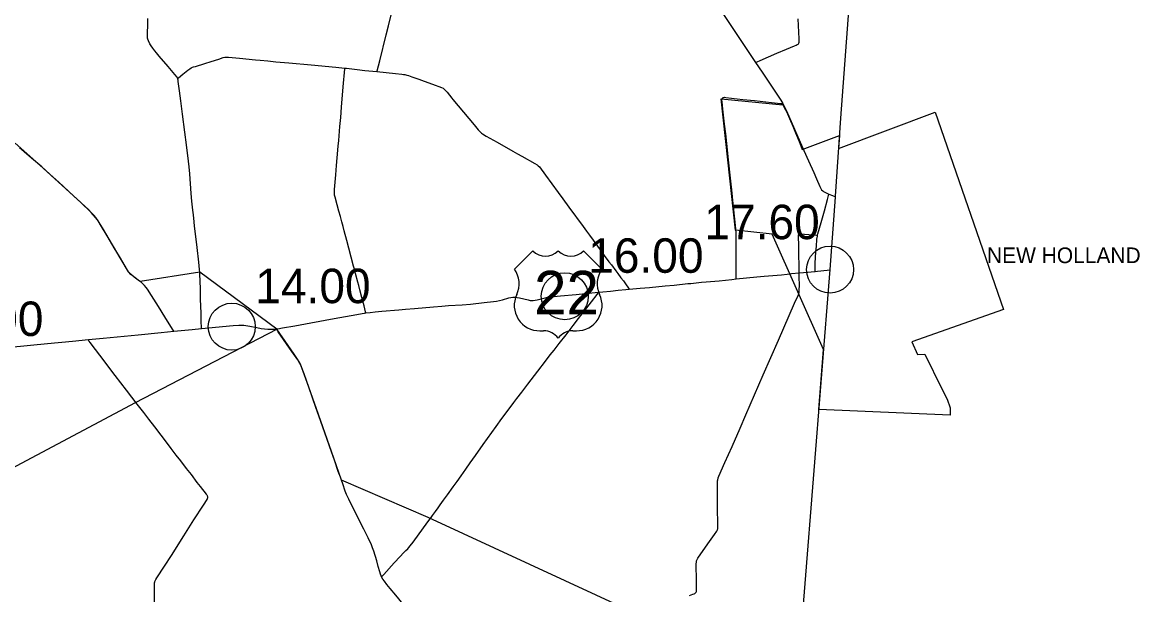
# Model space of a CAD drawing. Extents: x 1597222 to 1925846, y 496284 to 911751.
# Drawn here: x 1727439 to 1763107, y 556061 to 574335 of the extents above; entities that cross this region are included whole.
import ezdxf

# ---------------------------------------------------------------- set-up
doc = ezdxf.new("R2010")
doc.units = 0
for name, color, linetype in [('Default', 7, 'Continuous'), ('GM_X_City_Street', 7, 'Continuous'), ('GM_X_Corporation', 7, 'Continuous'), ('GM_X_Corporation_Text', 7, 'Continuous'), ('GM_X_County', 7, 'Continuous'), ('GM_X_County_Road', 7, 'Continuous'), ('GM_X_Township', 7, 'Continuous'), ('GM_X_Township_Road', 7, 'Continuous'), ('GM_X_US_Route', 7, 'Continuous'), ('GM_X_US_Shield', 7, 'Continuous')]:
    doc.layers.add(name, color=color, linetype=linetype)

msp = doc.modelspace()

# ---------------------------------------------------------------- linework, layer by layer
at = {"layer": 'Default'}
for centre in [(1753223, 566439), (1753223, 566439), (1744754, 565588), (1744754, 565588), (1734126, 564618), (1734126, 564618)]:
    msp.add_circle(centre, 750, dxfattribs=at)
at = {"layer": 'GM_X_City_Street'}
for points in [[(1752369, 570291), (1752389, 570247), (1752536, 569913), (1752703, 569539), (1752788, 569343), (1752900, 569089), (1752929, 569031), (1752955, 568990), (1752988, 568955), (1753013, 568935), (1753055, 568910), (1753188, 568853)], [(1752825, 567538), (1752836, 567586), (1752941, 567949), (1753043, 568312), (1753145, 568676), (1753188, 568853)], [(1753188, 568853), (1753301, 568804), (1753395, 568764)], [(1752239, 566334), (1752234, 566572), (1752227, 566915), (1752223, 567182), (1752217, 567525), (1752218, 567535), (1752218, 567543), (1752220, 567550), (1752221, 567555), (1752223, 567560), (1752226, 567566), (1752230, 567571), (1752235, 567575), (1752242, 567580), (1752251, 567584), (1752260, 567585), (1752270, 567586), (1752550, 567560), (1752746, 567546), (1752795, 567542), (1752825, 567538)], [(1752750, 566381), (1752750, 566403), (1752748, 566509), (1752749, 566657), (1752758, 566820), (1752774, 567017), (1752787, 567180), (1752806, 567409), (1752819, 567506), (1752825, 567538)], [(1752226, 565670), (1752228, 565675), (1752232, 565692), (1752235, 565703), (1752237, 565717), (1752239, 565733), (1752240, 565747), (1752241, 565777), (1752243, 565958), (1752242, 566185), (1752239, 566334)]]:
    msp.add_lwpolyline(points, dxfattribs=at)
at = {"layer": 'GM_X_Corporation'}
msp.add_lwpolyline([(1749745, 571890), (1751716, 571701), (1751801, 571545), (1751863, 571416), (1751961, 571194), (1752034, 571019), (1752121, 570810), (1752184, 570658), (1752255, 570482), (1752338, 570280), (1753522, 570727), (1753491, 570310), (1756577, 571472), (1758765, 565171), (1755833, 564137), (1756019, 563730), (1756253, 563741), (1756795, 562636), (1756958, 562307), (1757061, 562024), (1757061, 561796), (1752864, 561969), (1753016, 563885), (1751378, 567567), (1750207, 567702), (1749959, 569949)], close=True, dxfattribs=at)
at = {"layer": 'GM_X_County'}
msp.add_lwpolyline([(1724957, 620538), (1728386, 620349), (1731998, 620173), (1732995, 620100), (1742304, 619412), (1747296, 619048), (1751520, 618741), (1756758, 618359), (1755763, 604727), (1755032, 592905), (1754900, 590773), (1754843, 589851), (1754339, 581698), (1753562, 571274), (1753386, 568784), (1753383, 568749), (1753220, 566444), (1752151, 553079)], dxfattribs=at)
at = {"layer": 'GM_X_County_Road'}
for points in [[(1749047, 575739), (1749287, 575381), (1749764, 574674), (1749864, 574524), (1750804, 573121), (1750848, 573055)], [(1750848, 573055), (1751060, 572740), (1751399, 572237), (1751653, 571854), (1751721, 571742)], [(1751721, 571742), (1751748, 571684), (1751828, 571510), (1752348, 570341), (1752369, 570291)], [(1731184, 566070), (1731014, 566199), (1730924, 566270), (1730875, 566314), (1730843, 566352), (1730797, 566420), (1730537, 566857), (1730370, 567140), (1730144, 567521), (1729934, 567872), (1729855, 567997), (1729780, 568104), (1729717, 568180), (1729640, 568264), (1729547, 568356), (1729197, 568679), (1728932, 568923), (1728727, 569112), (1728512, 569314), (1728317, 569489), (1728058, 569716), (1727734, 569993), (1727499, 570198), (1727353, 570330)], [(1732277, 564471), (1732256, 564503), (1732176, 564627), (1731988, 564927), (1731782, 565261), (1731566, 565608), (1731434, 565815), (1731396, 565868), (1731344, 565931), (1731299, 565977), (1731228, 566036), (1731184, 566070)], [(1748738, 556034), (1748846, 556072), (1748891, 556091), (1748905, 556100), (1748917, 556109), (1748929, 556119), (1748939, 556131), (1748948, 556144), (1748955, 556160), (1748959, 556174), (1748962, 556187), (1748964, 556205), (1748965, 556270), (1748957, 556631), (1748954, 556910), (1748952, 557041), (1748954, 557070), (1748955, 557091), (1748959, 557116), (1748964, 557140), (1748973, 557167), (1748981, 557187), (1749006, 557231), (1749098, 557367), (1749370, 557757), (1749530, 557985), (1749605, 558093), (1749626, 558131), (1749632, 558145), (1749636, 558160), (1749641, 558184), (1749643, 558213), (1749643, 558312), (1749635, 558820), (1749631, 559099), (1749629, 559230), (1749627, 559427), (1749626, 559591), (1749629, 559674), (1749632, 559700), (1749636, 559723), (1749641, 559746), (1749648, 559770), (1749657, 559794), (1749678, 559848), (1749870, 560283), (1750096, 560793), (1750353, 561379), (1750536, 561800), (1751092, 563079), (1751334, 563636), (1751578, 564192), (1752094, 565363), (1752205, 565613), (1752226, 565670)], [(1737623, 559721), (1737591, 559812), (1737526, 559998), (1737410, 560322), (1737252, 560771), (1737155, 561050), (1736965, 561593), (1736806, 562041), (1736581, 562691), (1736433, 563108), (1736343, 563355), (1736311, 563431), (1736299, 563455), (1736280, 563489), (1736236, 563559), (1736047, 563827), (1735610, 564450), (1735581, 564499), (1735562, 564549)], [(1731010, 562272), (1730938, 562367), (1730767, 562588), (1730588, 562822), (1730407, 563055), (1730267, 563237), (1730048, 563524), (1729772, 563891), (1729601, 564112), (1729574, 564153), (1729563, 564168), (1729546, 564204)], [(1731065, 562201), (1731010, 562272)], [(1731658, 555625), (1731657, 556314), (1731657, 556397), (1731660, 556424), (1731663, 556446), (1731667, 556462), (1731670, 556469), (1731673, 556478), (1731682, 556498), (1731693, 556520), (1731704, 556541), (1731736, 556594), (1731975, 556967), (1732196, 557312), (1732590, 557936), (1732917, 558448), (1733219, 558916), (1733335, 559096), (1733349, 559125), (1733354, 559140), (1733356, 559147), (1733357, 559156), (1733358, 559162), (1733358, 559170), (1733356, 559186), (1733353, 559201), (1733349, 559213), (1733341, 559229), (1733314, 559270), (1733124, 559517), (1733024, 559647), (1732835, 559895), (1732684, 560089), (1732494, 560336), (1732354, 560518), (1732195, 560727), (1732005, 560974), (1731866, 561157), (1731666, 561417), (1731477, 561664), (1731317, 561872), (1731065, 562201)], [(1738909, 556629), (1738891, 556666), (1738873, 556712), (1738850, 556790), (1738803, 556964), (1738752, 557137), (1738660, 557452), (1738622, 557561), (1738584, 557652), (1738475, 557873), (1738337, 558153), (1738023, 558785), (1737862, 559108), (1737791, 559256), (1737748, 559363), (1737667, 559595), (1737623, 559721)], [(1739950, 555126), (1739799, 555418), (1739684, 555635), (1739662, 555671), (1739641, 555706), (1739601, 555758), (1739361, 556049), (1739180, 556261), (1739075, 556386), (1738995, 556490), (1738950, 556557), (1738909, 556629)]]:
    msp.add_lwpolyline(points, dxfattribs=at)
at = {"layer": 'GM_X_Township'}
for points in [[(1746884, 555518), (1740398, 558522), (1737625, 559721), (1737381, 560421), (1736826, 561994), (1736532, 562834), (1736317, 563420), (1736278, 563498), (1736222, 563582), (1736112, 563739), (1735825, 564152), (1735560, 564543), (1733105, 566354), (1731204, 566056), (1731180, 566074), (1730899, 566287), (1730833, 566366), (1730557, 566820), (1730003, 567769), (1729838, 568031), (1729641, 568263), (1729309, 568580), (1727867, 569889), (1727212, 570476)], [(1720963, 556836), (1731052, 562196), (1735560, 564543)]]:
    msp.add_lwpolyline(points, dxfattribs=at)
at = {"layer": 'GM_X_Township_Road'}
for points in [[(1738759, 572761), (1738766, 572788), (1738846, 573107), (1739052, 573934), (1739123, 574221), (1739251, 574747), (1739500, 575751), (1739569, 576022), (1739604, 576182), (1739634, 576343), (1739662, 576505), (1739666, 576531)], [(1732400, 572543), (1732394, 572555), (1732387, 572567), (1732377, 572582), (1732303, 572671), (1732092, 572922), (1731806, 573260), (1731722, 573360), (1731670, 573422), (1731600, 573512), (1731554, 573581), (1731514, 573652), (1731471, 573741), (1731447, 573802), (1731439, 573833), (1731436, 573849), (1731433, 573867), (1731432, 573879), (1731432, 573897), (1731436, 574028), (1731443, 574208), (1731450, 574454)], [(1750848, 573055), (1750892, 573075), (1750997, 573121), (1751254, 573231), (1751525, 573346), (1751828, 573474), (1752085, 573582), (1752146, 573608), (1752175, 573622), (1752189, 573631), (1752202, 573640), (1752214, 573652), (1752224, 573665), (1752231, 573679), (1752235, 573695), (1752238, 573711), (1752240, 573744), (1752238, 573810), (1752204, 574446)], [(1732400, 572543), (1732427, 572565), (1732566, 572678), (1732718, 572803), (1732783, 572852), (1732825, 572878), (1732848, 572890), (1732870, 572899), (1732908, 572912), (1732963, 572930), (1733261, 573021), (1733465, 573084), (1733715, 573163), (1733855, 573209), (1733903, 573219), (1733925, 573222), (1733952, 573225), (1734017, 573225), (1734376, 573189), (1734883, 573140), (1735029, 573128), (1735273, 573105), (1735535, 573079), (1735942, 573039), (1736661, 572973), (1737445, 572902), (1737733, 572874)], [(1738409, 565055), (1738399, 565092), (1738350, 565282), (1738278, 565551), (1738215, 565789), (1738179, 565932), (1738149, 566043), (1738078, 566313), (1738048, 566423), (1738014, 566550), (1737938, 566835), (1737863, 567120), (1737796, 567374), (1737715, 567675), (1737676, 567817), (1737638, 567960), (1737591, 568134), (1737543, 568307), (1737487, 568513), (1737422, 568750), (1737408, 568814), (1737402, 568863), (1737400, 568883), (1737400, 568912), (1737401, 568939), (1737405, 568994), (1737446, 569468), (1737471, 569762), (1737492, 570007), (1737525, 570383), (1737540, 570563), (1737577, 571004), (1737602, 571298), (1737629, 571625), (1737662, 572017), (1737693, 572393), (1737721, 572736), (1737731, 572851), (1737733, 572874)], [(1737733, 572874), (1737788, 572868), (1738130, 572829), (1738374, 572802), (1738759, 572761)], [(1733105, 566353), (1733099, 566445), (1733075, 566673), (1733019, 567146), (1732959, 567668), (1732940, 567830), (1732925, 567961), (1732898, 568189), (1732879, 568335), (1732845, 568629), (1732826, 568874), (1732781, 569496), (1732764, 569725), (1732746, 569905), (1732678, 570425), (1732624, 570832), (1732553, 571402), (1732495, 571825), (1732454, 572153), (1732417, 572445), (1732410, 572493), (1732405, 572524), (1732401, 572540), (1732400, 572543)], [(1738759, 572761), (1739352, 572698), (1739550, 572678), (1739606, 572672), (1739650, 572667), (1739679, 572661), (1739708, 572652), (1739767, 572636), (1739869, 572600), (1740100, 572517), (1740269, 572457), (1740531, 572360), (1740824, 572255), (1740868, 572234), (1740895, 572216), (1740930, 572181), (1740999, 572101), (1741152, 571914), (1741184, 571876), (1741863, 571058), (1741989, 570907), (1742055, 570834), (1742092, 570801), (1742132, 570772), (1742244, 570705), (1742602, 570504), (1743101, 570221), (1743244, 570141), (1743387, 570061), (1743802, 569829), (1743873, 569787), (1743911, 569757), (1743944, 569720), (1744139, 569456), (1744545, 568900), (1744691, 568703), (1744885, 568438), (1745338, 567814), (1745444, 567669), (1745541, 567536), (1745657, 567377), (1745882, 567074), (1746018, 566889), (1746165, 566693), (1746244, 566588), (1746381, 566404), (1746450, 566313), (1746548, 566181), (1746626, 566076), (1746714, 565956), (1746770, 565877), (1746792, 565849), (1746810, 565812)], [(1750221, 567701), (1750219, 567731), (1750198, 567957), (1750135, 568544), (1750087, 568984), (1750056, 569261), (1749983, 569945), (1749926, 570466), (1749892, 570776), (1749858, 571085), (1749804, 571558), (1749776, 571802), (1749771, 571852), (1749771, 571869), (1749773, 571886), (1749779, 571902), (1749789, 571916), (1749801, 571928), (1749816, 571936), (1749833, 571940), (1749850, 571941), (1749900, 571937), (1750258, 571895), (1750438, 571876), (1750812, 571835), (1751350, 571776), (1751643, 571743), (1751686, 571741), (1751721, 571742)], [(1750224, 566140), (1750224, 566146), (1750224, 566192), (1750225, 566372), (1750227, 566667), (1750225, 566929), (1750225, 567142), (1750223, 567437), (1750222, 567650), (1750221, 567701)], [(1733160, 564557), (1733158, 564592), (1733157, 564608), (1733152, 564757), (1733144, 565051), (1733131, 565494), (1733123, 565838), (1733107, 566298), (1733105, 566353)], [(1740884, 559073), (1741014, 559252), (1741197, 559504), (1741322, 559677), (1741446, 559850), (1741597, 560064), (1741738, 560265), (1741909, 560505), (1742154, 560854), (1742286, 561042), (1742428, 561242), (1742560, 561430), (1742744, 561681), (1742978, 561997), (1743127, 562192), (1743225, 562324), (1743385, 562531), (1743576, 562777), (1743894, 563194), (1744144, 563519), (1744294, 563714), (1744415, 563868), (1744573, 564077), (1744795, 564361), (1745025, 564659), (1745196, 564879), (1745608, 565410), (1745790, 565642), (1745812, 565680), (1745822, 565720)], [(1740465, 558493), (1740531, 558584), (1740626, 558717), (1740713, 558836), (1740779, 558927), (1740884, 559073)], [(1738909, 556629), (1738983, 556705), (1739311, 557072), (1739496, 557280), (1739611, 557397), (1739686, 557467), (1739744, 557526), (1739782, 557568), (1739823, 557620), (1739911, 557737), (1740388, 558385), (1740455, 558478), (1740465, 558493)]]:
    msp.add_lwpolyline(points, dxfattribs=at)
at = {"layer": 'GM_X_US_Route'}
for points in [[(1751943, 566306), (1751990, 566311), (1752239, 566334), (1752515, 566359), (1752728, 566379), (1752750, 566381), (1752826, 566389), (1753127, 566420), (1753220, 566430)], [(1746216, 565756), (1746462, 565780), (1746707, 565802), (1746810, 565812), (1747164, 565846), (1747458, 565873), (1747964, 565922), (1748242, 565948), (1748683, 565991), (1748775, 566000), (1749124, 566036), (1749268, 566049)], [(1749268, 566049), (1749679, 566086), (1750087, 566126), (1750224, 566140), (1750887, 566204), (1751116, 566226), (1751671, 566278), (1751851, 566298), (1751943, 566306)], [(1744219, 565562), (1744306, 565574), (1744617, 565604), (1745123, 565650), (1745822, 565720), (1745972, 565733), (1746216, 565756)], [(1738352, 565046), (1738362, 565048), (1738409, 565055), (1738540, 565074), (1738703, 565091), (1738915, 565108), (1739455, 565155), (1739667, 565173), (1739962, 565199), (1740567, 565247), (1740828, 565271), (1741040, 565289), (1741482, 565319), (1741744, 565340), (1742184, 565389), (1742479, 565424)], [(1742479, 565424), (1742576, 565435), (1742673, 565451), (1742769, 565474), (1742973, 565535), (1743037, 565549), (1743102, 565557), (1743167, 565559), (1743231, 565554), (1743312, 565539), (1743582, 565470), (1743647, 565458), (1743696, 565453), (1743746, 565454), (1743812, 565460), (1743876, 565473), (1744130, 565543), (1744209, 565560), (1744219, 565562)], [(1734927, 564589), (1735060, 564564), (1735174, 564546), (1735272, 564537), (1735371, 564535), (1735486, 564540), (1735562, 564549), (1735600, 564553), (1735746, 564578), (1736133, 564649), (1736650, 564743), (1737393, 564876), (1737941, 564976), (1738352, 565046)], [(1727049, 563961), (1728242, 564078), (1729042, 564154), (1729546, 564204), (1730022, 564251), (1731132, 564358), (1731867, 564431), (1732277, 564471), (1732863, 564528), (1733160, 564557), (1734169, 564654), (1734349, 564668), (1734447, 564669), (1734511, 564663), (1734705, 564630), (1734927, 564589)]]:
    msp.add_lwpolyline(points, dxfattribs=at)
at = {"layer": 'GM_X_US_Shield'}
for p, q in [((1743732, 567038), (1743152, 566458)), ((1745937, 566458), (1745357, 567038)), ((1743964, 564485), (1744080, 564485)), ((1745009, 564485), (1745125, 564485))]:
    msp.add_line(p, q, dxfattribs=at)
for centre, radius, start, end in [((1744138, 567452), 580, 225.573, 314.427), ((1744951, 567452), 580, 225.573, 314.427), ((1742487, 565992), 812, 334.5471, 35.0009), ((1746602, 565992), 812, 144.9991, 205.4529), ((1743955, 565297), 812, 154.8319, 270.6383), ((1745134, 565297), 812, 269.3617, 25.1681), ((1744080, 563905), 580, 36.8699, 90), ((1745009, 563905), 580, 90, 143.1301)]:
    msp.add_arc(centre, radius, start, end, dxfattribs=at)

# ---------------------------------------------------------------- texts
at = {"layer": 'Default'}
for s, p in [('17.60', (1749212, 567411)), ('17.60', (1749212, 567411)), ('16.00', (1745504, 566338)), ('16.00', (1745504, 566338)), ('14.00', (1734876, 565368)), ('14.00', (1734876, 565368)), ('12.00', (1724432, 564320)), ('12.00', (1724432, 564320))]:
    msp.add_text(s, height=1100, dxfattribs=at).set_placement(p)
at = {"layer": 'GM_X_Corporation_Text'}
msp.add_text('NEW HOLLAND', height=500, rotation=0, dxfattribs=at).set_placement((1758235, 566647))
at = {"layer": 'GM_X_US_Shield'}
msp.add_text('22', height=1392.2, dxfattribs=at).set_placement((1743774, 565007))

doc.saveas('drawing.dxf')
